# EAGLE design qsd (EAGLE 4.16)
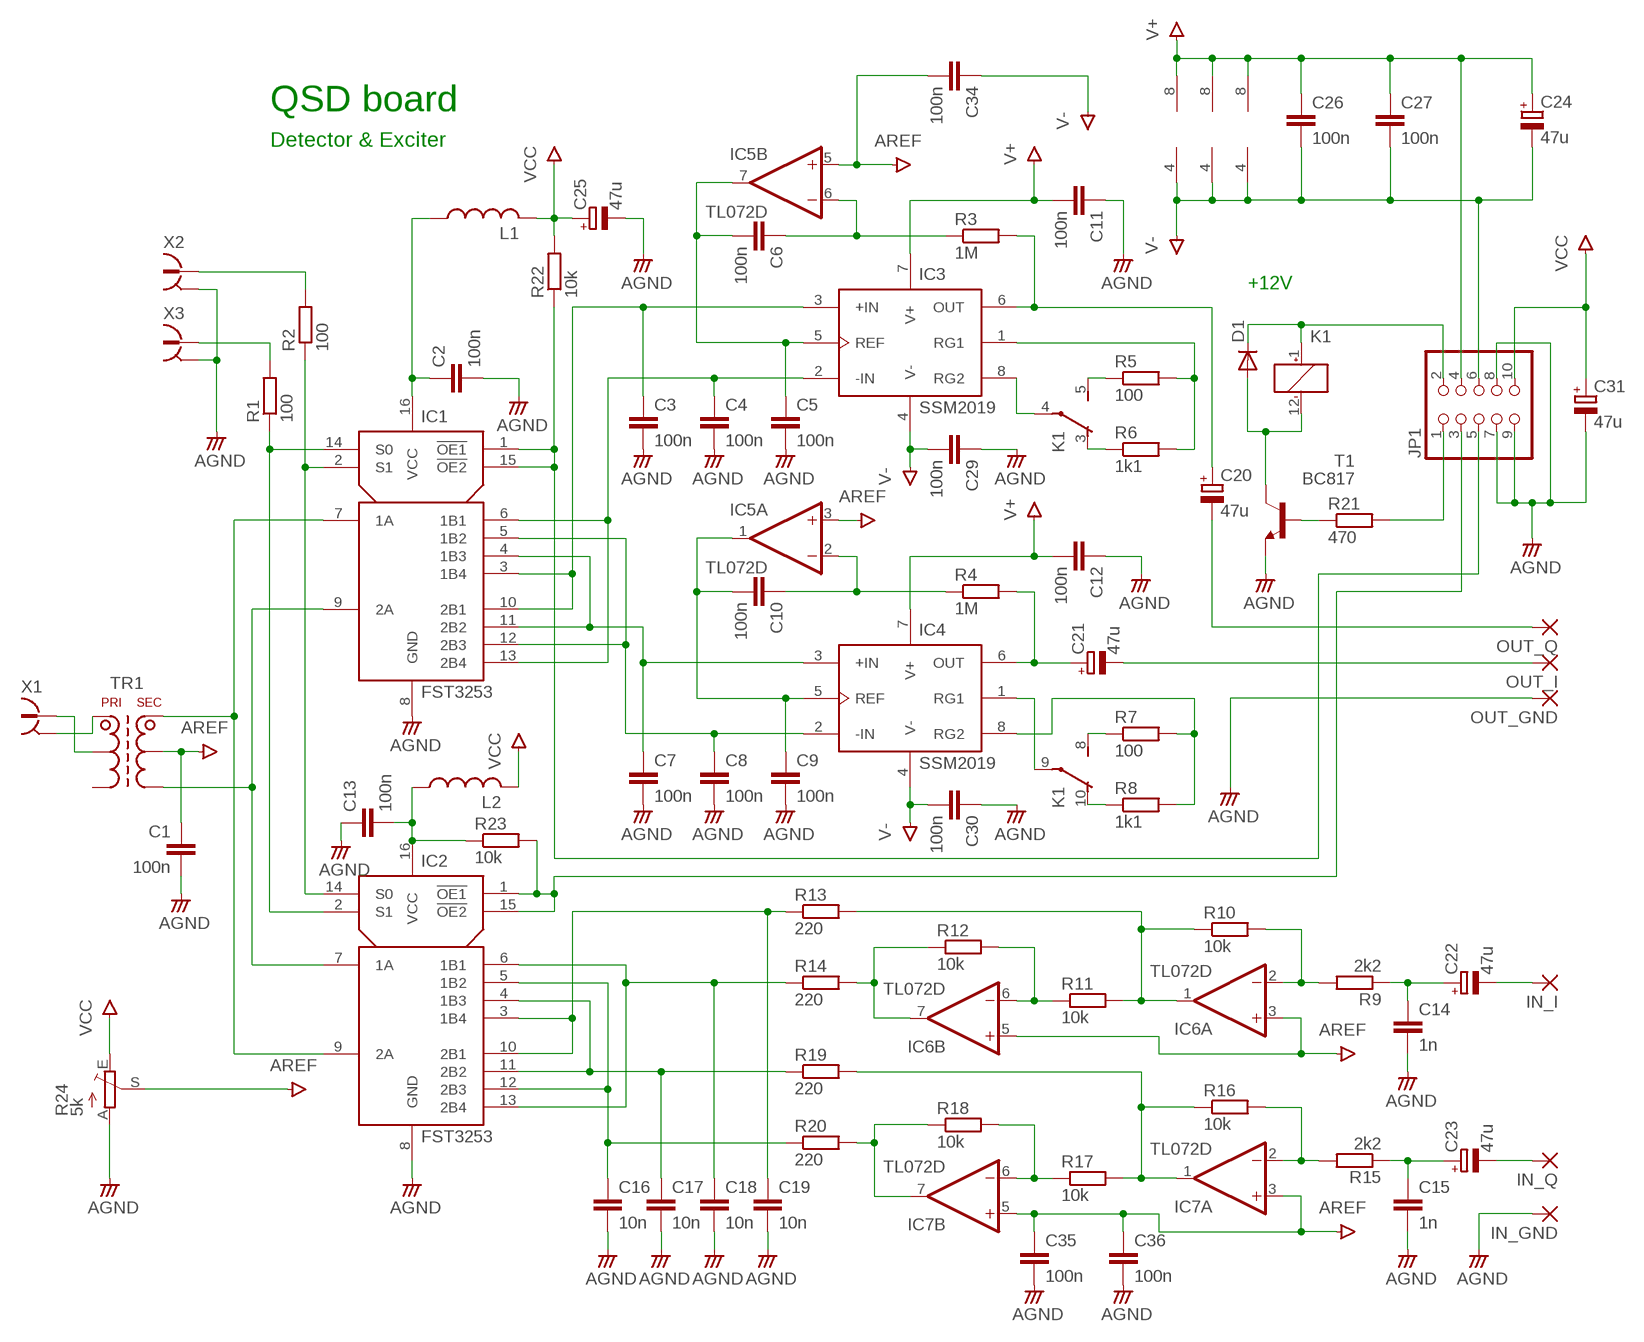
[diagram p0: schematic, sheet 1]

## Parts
C1  100n  C-EUC1206  [C1206]
C2  100n  C-EUC1206  [C1206]
C3  100n  C-EUC1206  [C1206]
C4  100n  C-EUC1206  [C1206]
C5  100n  C-EUC1206  [C1206]
C6  100n  C-EUC1206  [C1206]
C7  100n  C-EUC1206  [C1206]
C8  100n  C-EUC1206  [C1206]
C9  100n  C-EUC1206  [C1206]
C10  100n  C-EUC1206  [C1206]
C11  100n  C-EUC1206  [C1206]
C12  100n  C-EUC1206  [C1206]
C13  100n  C-EUC1206  [C1206]
C14  1n  C-EUC0805  [C0805]
C15  1n  C-EUC0805  [C0805]
C16  10n  C-EUC1206  [C1206]
C17  10n  C-EUC1206  [C1206]
C18  10n  C-EUC1206  [C1206]
C19  10n  C-EUC1206  [C1206]
C20  47u  CPOL-EUC  [PANASONIC_C]
C21  47u  CPOL-EUC  [PANASONIC_C]
C22  47u  CPOL-EUC  [PANASONIC_C]
C23  47u  CPOL-EUC  [PANASONIC_C]
C24  47u  CPOL-EUC  [PANASONIC_C]
C25  47u  CPOL-EUC  [PANASONIC_C]
C26  100n  C-EUC1206  [C1206]
C27  100n  C-EUC1206  [C1206]
C29  100n  C-EUC1206  [C1206]
C30  100n  C-EUC1206  [C1206]
C31  47u  CPOL-EUC  [PANASONIC_C]
C34  100n  C-EUC1206  [C1206]
C35  100n  C-EUC1206  [C1206]
C36  100n  C-EUC1206  [C1206]
D1  PMLL4150  [SOD80C]
IC1  FST3253  [SO16]
IC2  FST3253  [SO16]
IC3  SSM2019  [SO08]
IC4  SSM2019  [SO08]
IC5  TL072D  [SO08]
IC6  TL072D  [SO08]
IC7  TL072D  [SO08]
IN_GND  SMD2  [SMD1,27-2,54]
IN_I  SMD2  [SMD1,27-2,54]
IN_Q  SMD2  [SMD1,27-2,54]
JP1  PINHD-2X5  [2X05]
K1  TX2SOSA-12V  [TX2SA]
L1  L-US0207/7  [0207/7]
L2  L-US0207/7  [0207/7]
OUT_GND  SMD2  [SMD1,27-2,54]
OUT_I  SMD2  [SMD1,27-2,54]
OUT_Q  SMD2  [SMD1,27-2,54]
R1  100  R-EU_R1206  [R1206]
R2  100  R-EU_R1206  [R1206]
R3  1M  R-EU_R1206  [R1206]
R4  1M  R-EU_R1206  [R1206]
R5  100  R-EU_R1206  [R1206]
R6  1k1  R-EU_R1206  [R1206]
R7  100  R-EU_R1206  [R1206]
R8  1k1  R-EU_R1206  [R1206]
R9  2k2  R-EU_R1206  [R1206]
R10  10k  R-EU_R1206  [R1206]
R11  10k  R-EU_R1206  [R1206]
R12  10k  R-EU_R1206  [R1206]
R13  220  R-EU_R1206  [R1206]
R14  220  R-EU_R1206  [R1206]
R15  2k2  R-EU_R1206  [R1206]
R16  10k  R-EU_R1206  [R1206]
R17  10k  R-EU_R1206  [R1206]
R18  10k  R-EU_R1206  [R1206]
R19  220  R-EU_R1206  [R1206]
R20  220  R-EU_R1206  [R1206]
R21  470  R-EU_R1206  [R1206]
R22  10k  R-EU_R1206  [R1206]
R23  10k  R-EU_R1206  [R1206]
R24  5k  TRIM_EU-S64W  [S64W]
T1  BC817  BC817-16-NPN-SOT23-BEC  [SOT23-BEC]
TR1  TT1-6  [MINICIRCUITS-W38]
X1  ST-SMB-V  [ST-SMB-V]
X2  ST-SMB-V  [ST-SMB-V]
X3  ST-SMB-V  [ST-SMB-V]

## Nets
AREF: C1.1 C34.2 C35.1 C36.1 IC5.3(A:+IN) IC5.5(B:+IN) IC6.3(A:+IN) IC6.5(B:+IN) IC7.3(A:+IN) IC7.5(B:+IN) R24.S TR1.2(ST)
N$1: TR1.5(PT) X1.1
N$2: TR1.4(P1) X1.2(GND)
N$3: IC1.14(S0) IC2.2(S1) R1.1
N$4: IC1.2(S1) IC2.14(S0) R2.1
N$5: IC1.7(1A) IC2.9(2A) TR1.3(S1)
N$6: IC1.9(2A) IC2.7(1A) TR1.1(S2)
N$7: IC1.1(!OE1) IC1.15(!OE2) JP1.5 R22.1
N$8: IC2.1(!OE1) IC2.15(!OE2) JP1.3 R23.2
N$9: C18.1 IC2.6(1B1) IC2.13(2B4) R14.1
N$10: C19.1 IC2.3(1B4) IC2.10(2B1) R13.1
N$14: C7.1 IC1.4(1B3) IC1.11(2B2) IC4.3(+IN)
N$15: C8.1 IC1.5(1B2) IC1.12(2B3) IC4.2(-IN)
N$16: C4.1 IC1.6(1B1) IC1.13(2B4) IC3.2(-IN)
N$17: C2.1 IC1.16(VCC) L1.1
N$19: C6.1 IC5.6(B:-IN) R3.1
N$23: C21.+ IC4.6(OUT) R4.2
N$24: IC3.8(RG2) K1.4(1:P)
N$25: R2.2 X2.1
N$26: R1.2 X3.1
N$28: K1.8(2:S) R7.1
N$29: K1.10(2:O) R8.1
N$30: K1.3(1:O) R6.1
N$31: K1.5(1:S) R5.1
N$32: IC4.8(RG2) R7.2 R8.2
N$33: IC3.1(RG1) R5.2 R6.2
N$35: D1.A K1.12(_:-) T1.C
N$36: C13.2 IC2.16(VCC) L2.1 R23.1
N$37: IC7.6(B:-IN) R17.1 R18.2
N$38: C15.1 C23.+ R15.1
N$39: IC7.1(A:OUT) R16.1 R17.2 R19.2
N$40: IC6.2(A:-IN) R9.2 R10.2
N$41: IC6.6(B:-IN) R11.1 R12.2
N$42: IC6.7(B:OUT) R12.1 R14.2
N$43: IC6.1(A:OUT) R10.1 R11.2 R13.2
N$45: IC7.7(B:OUT) R18.1 R20.2
N$46: C14.1 C22.+ R9.1
N$47: C20.- OUT_Q.1(P)
N$48: C21.- OUT_I.1(P)
N$49: C20.+ IC3.6(OUT) R3.2
N$50: C22.- IN_I.1(P)
N$51: C23.- IN_Q.1(P)
N$53: R21.1 T1.B
N$55: JP1.1 R21.2
N$98: C17.1 IC2.4(1B3) IC2.11(2B2) R19.1
N$106: C16.1 IC2.5(1B2) IC2.12(2B3) R20.1
N$132: C9.1 C10.2 IC4.5(REF) IC5.1(A:OUT)
N$135: C10.1 IC5.2(A:-IN) R4.1
N$161: C24.- C26.2 C27.2 C29.2 C30.2 C34.1 IC3.4(V-) IC4.4(V-) IC5.4(P:V-) IC6.4(P:V-) IC7.4(P:V-) JP1.6 ; supply symbol labelled V-
N$207: D1.C JP1.2 K1.1(_:+)
N$211: C25.+ C31.+ JP1.10 L1.2 L2.2 R22.2 R24.E ; supply symbol labelled VCC
N$218: C11.2 C12.2 C24.+ C26.1 C27.1 IC3.7(V+) IC4.7(V+) IC5.8(P:V+) IC6.8(P:V+) IC7.8(P:V+) JP1.4 ; supply symbol labelled V+
N$221: IC4.1(RG1) K1.9(2:P)
N$226: C5.1 C6.2 IC3.5(REF) IC5.7(B:OUT)
N$248: IC7.2(A:-IN) R15.2 R16.2
N$315: C1.2 C2.2 C3.2 C4.2 C5.2 C7.2 C8.2 C9.2 C11.1 C12.1 C13.1 C14.2 C15.2 C16.2 C17.2 C18.2 C19.2 C25.- C29.1 C30.1 C31.- C35.2 C36.2 IC1.8(GND) IC2.8(GND) IN_GND.1(P) JP1.7 JP1.8 JP1.9 OUT_GND.1(P) R24.A T1.E X2.2(GND) X3.2(GND) ; supply symbol labelled AGND
N$325: C3.1 IC1.3(1B4) IC1.10(2B1) IC3.3(+IN)
Unconnected: TR1.6(P2)

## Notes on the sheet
- QSD board
- Detector & Exciter
- +12V

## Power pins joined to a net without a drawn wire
N$315: X1.3(GND) X1.4(GND) X1.5(GND) X2.3(GND) X2.4(GND) X2.5(GND) X3.3(GND) X3.4(GND) X3.5(GND)

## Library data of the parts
C1-C19 C26 C27 C29 C30 C34-C36 = rcl:C-EU: CAPACITOR, European symbol
C20-C25 C31 = rcl:CPOL-EU: POLARIZED CAPACITOR, European symbol
D1 = diode:PMLL4150: DIODE
IC1 IC2 = receiver:FST3253
IC3 IC4 = receiver:SSM2019
IC5-IC7 = linear:TL072: OP AMP
IN_GND IN_I IN_Q OUT_GND OUT_I OUT_Q = wirepad:SMD2: SMD PAD
JP1 = pinhead:PINHD-2X5: PIN HEADER
K1 = relay:TX2SO?-*: 2 AMP. HIGH CAPACITY RELAY NAiS WITH HIGH SURGE VOLTAGE & HIGH BREAKDOWN VOLTAGE Source: http://www.mew-europe.com/.. en_ds_61022_0001.pdf
L1 L2 = rcl:L-US: INDUCTOR, American symbol
R1-R23 = rcl:R-EU_: RESISTOR, European symbol
R24 = pot:TRIM_EU-: POTENTIOMETER
T1 = transistor:*-NPN-: NPN Transistror
TR1 = receiver:TT1-6
X1-X3 = con-coax:ST-SMB-V: MALE SMB CONNECTOR Radiall distributor RS 193-8855G7

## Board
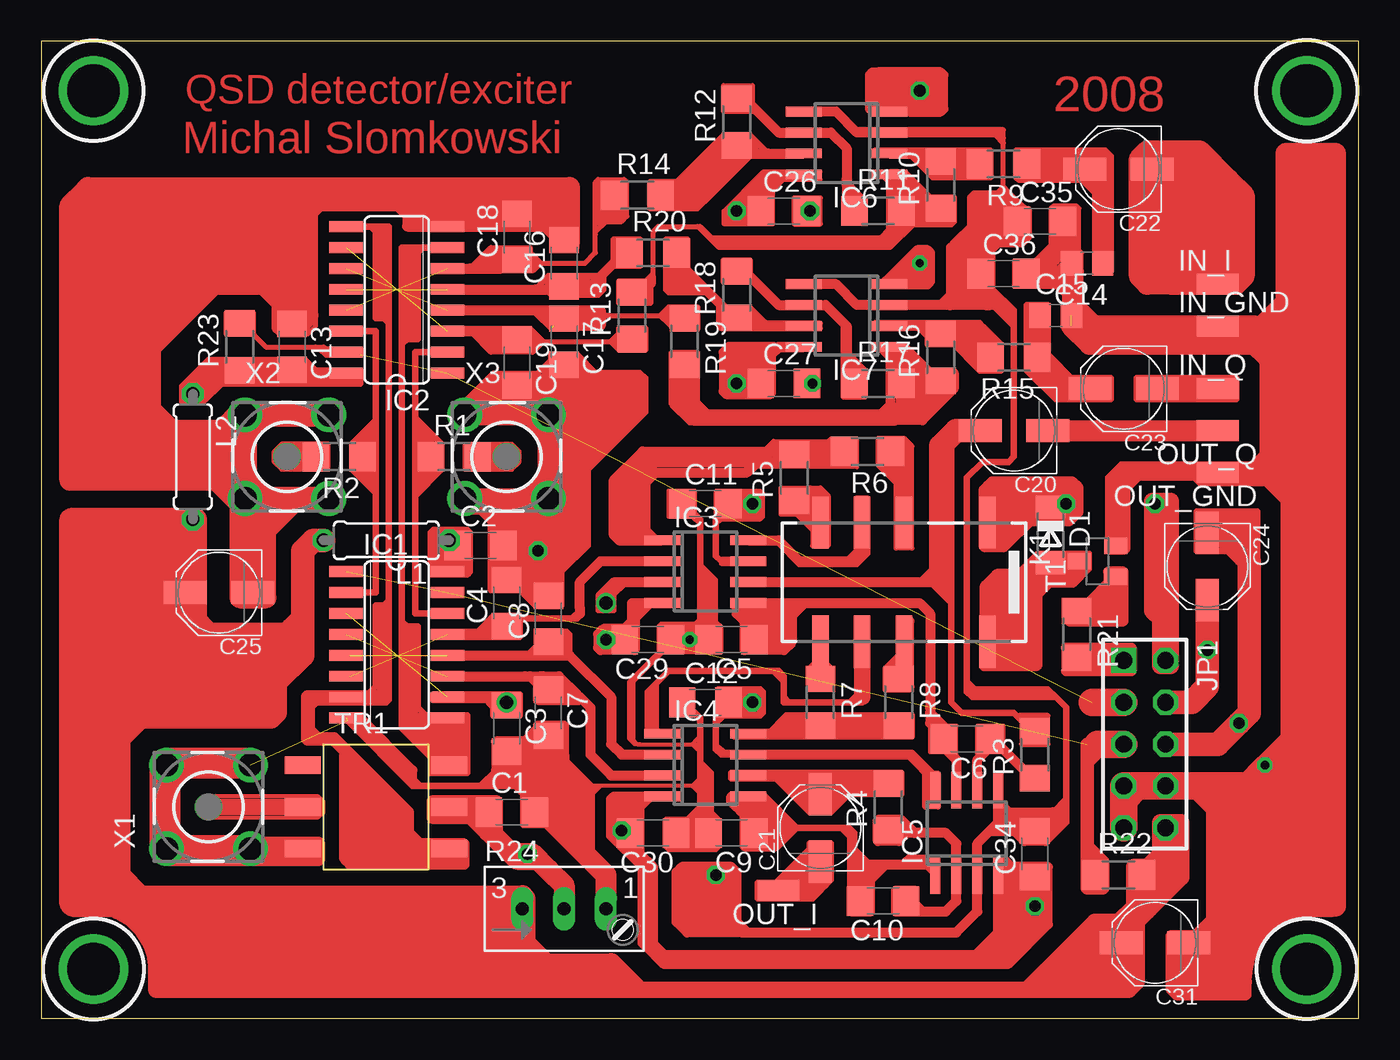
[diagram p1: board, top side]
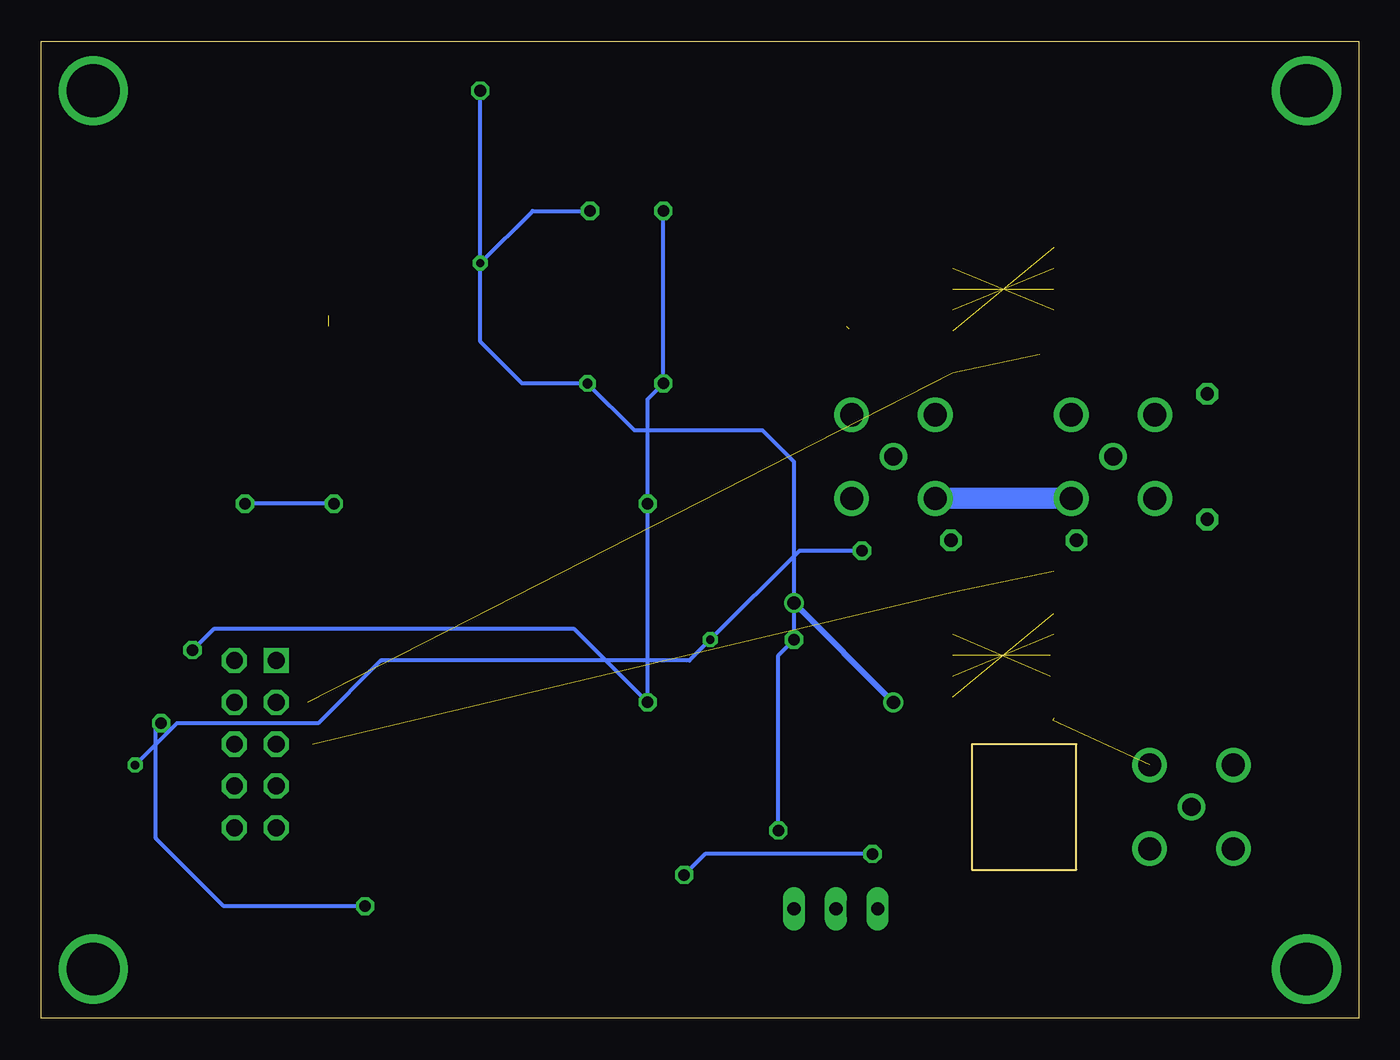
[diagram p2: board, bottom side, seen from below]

Size 79.99 x 59.36 mm. Coordinates in mm from the lower left corner, seen from the top.
Outline: 0,0 79.99,0 79.99,59.36 0,59.36 0,0
Copper layers (1*16): Top 0.035mm / dielectric 1.5mm / Bottom 0.035mm
Design rules "default": minimum track width 10mil, minimum drill 24mil, track to track 8mil, track to pad 8mil, pad to pad 8mil, via to via 8mil, smd to smd 8mil, copper to edge 40mil, drill to drill 8mil, minimum pad ring 10mil, minimum via ring 8mil, stop-mask expansion 4mil, vias tented up to drill 0mil, thermal gap 10mil

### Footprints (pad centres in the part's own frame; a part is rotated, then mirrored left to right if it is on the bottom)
C1206 = smd 1.6 x 1.8: 1 -1.4,0; 2 1.4,0
C0805 = smd 1.3 x 1.5: 1 -0.95,0; 2 0.95,0
PANASONIC_C = smd 2.6 x 1.4: + 2.05,0; - -2.05,0
SOD80C = smd 1.4 x 1.8: A 1.7,0; C -1.7,0
SO16 = smd 0.66 x 2.032: 1 -4.445,-3.073; 2 -3.175,-3.073; 3 -1.905,-3.073; 4 -0.635,-3.073; 5 0.635,-3.073; 6 1.905,-3.073; 7 3.175,-3.073; 8 4.445,-3.073; 9 4.445,3.073; 10 3.175,3.073; 11 1.905,3.073; 12 0.635,3.073; 13 -0.635,3.073; 14 -1.905,3.073; 15 -3.175,3.073; 16 -4.445,3.073
SO08 = smd 0.6 x 2.2: 1 -1.905,-2.6; 2 -0.635,-2.6; 3 0.635,-2.6; 4 1.905,-2.6; 5 1.905,2.6; 6 0.635,2.6; 7 -0.635,2.6; 8 -1.905,2.6
SMD1,27-2,54 = smd 1.27 x 2.54: 1 0,0
2X05 = drill 1.016 square: 1 -5.08,-1.27 | drill 1.016 octagon: 2 -5.08,1.27; 3 -2.54,-1.27; 4 -2.54,1.27; 5 0,-1.27; 6 0,1.27; 7 2.54,-1.27; 8 2.54,1.27; 9 5.08,-1.27; 10 5.08,1.27
TX2SA = smd 1 x 3.16: 1 -5.08,-3.62; 3 0,-3.62; 4 2.54,-3.62; 5 5.08,-3.62; 8 5.08,3.62; 9 2.54,3.62; 10 0,3.62; 12 -5.08,3.62
0207/7 = drill 0.813 octagon: 1 -3.81,0; 2 3.81,0
R1206 = smd 1.6 x 1.803: 1 -1.422,0; 2 1.422,0
S64W = drill 0.813 long: A 2.54,1.27; E -2.54,1.27; S 0,1.27
SOT23-BEC = smd 1 x 1.4: B -0.95,-1.1; C 0,1.1; E 0.95,-1.1
MINICIRCUITS-W38 = smd 1.067 x 2.184: 1 -2.54,6.35; 2 0,6.35; 3 2.54,6.35; 4 2.54,-2.54; 5 0,-2.54; 6 -2.54,-2.54
ST-SMB-V = drill 1.1 round: 1 0,0 | drill 1.4 round: 2 -2.54,2.54; 3 2.54,2.54; 4 2.54,-2.54; 5 -2.54,-2.54

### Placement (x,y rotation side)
C1  28.57,12.54 0 top
C2  26.66,28.73 0 top
C3  28.25,17.61 270 top
C4  28.25,25.23 90 top
C5  41.91,23.01 180 top
C6  56.19,16.98 180 top
C7  30.79,18.57 270 top
C8  30.79,24.28 90 top
C9  41.91,11.27 180 top
C10  51.11,7.14 180 top
C11  40.32,31.27 0 top
C12  40.32,19.2 0 top
C13  15.24,40.79 270 top
C14  63.5,45.87 180 top
C15  61.59,42.7 0 top
C16  31.74,45.87 90 top
C17  31.74,41.11 270 top
C18  28.89,47.46 90 top
C19  28.89,39.84 270 top
C20  59.05,35.71 180 top
C21  47.3,11.58 90 top
C22  65.4,51.59 180 top
C23  65.72,38.25 180 top
C24  70.8,27.46 270 top
C25  10.79,25.87 180 top
C26  45.08,49.05 0 top
C27  45.08,38.57 0 top
C29  36.83,23.01 180 top
C30  37.14,11.27 180 top
C31  67.62,4.6 180 top
C34  60.32,10 90 top
C35  60.64,48.41 0 top
C36  58.41,45.24 0 top
D1  61.27,29.36 270 top
IC1  21.58,22.7 270 top
IC2  21.58,43.65 90 top
IC3  40.32,27.14 270 top
IC4  40.32,15.39 270 top
IC5  56.19,11.27 0 top
IC6  48.89,53.17 90 top
IC7  48.89,42.7 90 top
IN_GND  71.43,42.06 270 top
IN_I  71.43,44.6 270 top
IN_Q  71.43,38.25 270 top
JP1  66.99,16.66 270 top
K1  52.38,26.5 180 top
L1  20.95,29.04 180 top
L2  9.2,34.12 270 top
OUT_GND  71.43,33.17 90 top
OUT_I  44.76,7.77 90 top
OUT_Q  71.43,35.71 90 top
R1  25.08,34.12 0 top
R2  18.09,34.12 180 top
R3  60.32,16.03 90 top
R4  51.43,12.85 90 top
R5  45.72,32.85 90 top
R6  50.16,34.44 180 top
R7  47.3,19.2 270 top
R8  52.07,19.2 270 top
R9  58.41,51.91 180 top
R10  54.61,50.63 90 top
R11  50.8,49.05 0 top
R12  42.22,54.45 90 top
R13  35.87,42.7 90 top
R14  36.19,50 0 top
R15  59.05,40.16 180 top
R16  54.61,40.16 90 top
R17  50.8,38.57 0 top
R18  42.22,43.97 90 top
R19  39.05,41.11 270 top
R20  37.14,46.51 0 top
R21  62.86,23.33 270 top
R22  65.4,8.73 0 top
R23  12.06,40.79 90 top
R24  31.74,5.39 0 top
T1  64.13,27.77 90 top
TR1  18.41,12.85 270 top
X1  10.16,12.85 90 top
X2  14.92,34.12 0 top
X3  28.25,34.12 0 top

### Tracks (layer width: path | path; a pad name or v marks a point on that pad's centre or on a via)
AREF  (via drill 0.7)
  Top 0.254: 28.73,9.84 28.89,10 v29.52,10 | 28.73,9.84
  Top 0.305: 58.1,53.81 58.41,53.49 58.41,53.17 | 58.41,50.32 58.41,53.17 | 58.41,53.17 58.41,53.97 49.53,53.97 | 58.41,53.17 | 58.41,53.17 57.94,53.65
  Top 0.406: 58.1,12.22 61.27,12.22 62.23,13.17 62.23,13.33 | 62.23,13.33 62.23,18.88 61.59,19.52 | 61.59,19.52 56.51,19.52 56.19,19.84 56.19,20.47 | 56.19,20.47 56.19,32.85 57.15,33.81 58.73,33.81 59.05,34.12 59.05,41.9 | 56.37,45 56.37,44.75 57.78,43.33 59.05,42.06 59.05,41.9 | 62.23,13.33 62.23,11.9 61.11,10.79 | 62.23,13.33 | 61.43,12.54 62.23,13.33 | 59.05,41.9 59.05,43.02 57.78,44.28 | 55.24,43.97 55.08,43.97 54.45,43.33 | 61.59,19.52 | 61.59,19.52 61.11,20 56.67,20 56.19,20.47
  Top 0.61: 58.1,13.17 58.1,12.22 58.1,11.9 57.78,11.58 | 57.78,11.58 56.83,10.63 IC5.3 56.83,6.5 55.56,5.23 42.86,5.23 | C34.2 57.65,11.4 57.78,11.58 | IC6.5 48.26,55.08 49.53,53.81 IC6.3 58.1,53.81 | IC7.5 48.26,44.6 49.53,43.33 IC7.3 54.45,43.33 55.08,43.33 | 58.41,49.05 58.41,48.41 57.15,47.14 | 58.41,49.05 58.41,50.32 | C36.1 56.37,45 55.24,44.6 55.24,44.44 | 55.08,43.33 55.24,43.33 55.24,43.97 55.24,44.44 | 58.41,49.05 C35.1 | 42.86,5.23 42.54,5.23 41.59,6.18 41.59,8.73 v40.95,8.73 | 58.1,13.17 IC5.5 | 58.1,13.17 58.73,12.54 61.43,12.54 | 42.86,5.23 42.22,5.87 42.22,8.88 41.91,9.2 38.89,9.2 38.57,8.88 38.57,5.87 39.21,5.23 42.86,5.23 | 58.41,50.32 | 58.41,50.32 59.53,49.21 | 59.53,49.21 | 59.53,49.21 59.69,49.05 59.84,49.05 59.84,47.46 59.53,47.14 | 58.41,47.14 59.53,47.14 | 57.15,47.14 58.41,47.14 | 58.41,47.14 58.1,47.14 57.62,46.67 57.62,43.49 | 57.3,43.33 55.08,43.33 | 57.3,43.33 57.62,43.33 | 57.78,43.33 57.3,43.33 | 55.56,47.14 57.15,47.14 | 55.56,47.14 55.24,46.82 55.24,44.44 | 58.41,50.32 58.1,50 56.67,50 56.51,49.84 56.51,48.41 | 56.51,48.41 56.51,48.09 55.56,47.14 | 56.51,48.41 56.51,47.3
  Top 0.813: 27.62,10.95 27.3,10.95 26.03,12.22 23.81,12.22 23.81,13.17 27.62,13.17 27.62,11.27
  Top 1.016: C1.1 26.98,12.54 26.66,12.85 TR1.2
  Top 1.27: C1.1 27.17,11.4 27.62,10.95 28.73,9.84 28.89,9.68 30.16,9.68 30.79,9.04 | 30.79,9.04 31.74,8.09 R24.S | 30.79,9.04 29.84,10 28.73,10
  Bottom 0.254: v40.95,8.73 39.68,10 v29.52,10
N$1
  Top 1.016: X1.1 TR1.5
N$2
  Top 1.016: X1.2 TR1.4
N$3
  Top 0.406: IC2.2 22.7,40.48 22.7,34.12 | 22.7,34.12 22.7,24.6 IC1.14 24.76,24.6 | 22.7,34.12 R1.1
N$4
  Top 0.406: IC2.14 20.31,41.74 20.31,36.35 | 20.31,31.9 20.31,25.87 IC1.2 | 20.31,31.9 20.31,34.12 | 20.31,34.12 20.31,36.35 | 20.31,34.12 R2.1 | 20.31,36.35 18.89,34.92 18.89,33.33 20.31,31.9
N$5
  Top 0.254: 17.14,16.98 16.5,17.61 16.5,18.88 | 16.5,18.88 16.5,19.2 | 16.5,18.88 16.82,19.2 20.95,19.2
  Top 0.406: 21.11,20 21.11,19.52 20.79,19.52 18.73,19.52 | 21.11,20 21.11,25.55 | 21.11,25.55 21.11,41.9 | 21.11,41.9 21.11,48.09 20,48.09 | 18.09,48.09 IC2.9 20,48.09 | 21.11,20 21.11,19.36 20.95,19.2 16.5,19.2 | 21.11,25.55 21.11,25.39 20.79,25.08 20.31,25.08 20.31,20.15 19.84,19.68 | 21.11,41.9 21.11,42.22 20.79,42.54 20.31,42.54 20.31,47.78 20,48.09
  Top 0.61: IC1.7 18.73,19.52 16.5,19.52 16.19,19.2 | 22.86,10.63 25.71,10.63 25.71,9.36 18.73,9.36 18.41,9.68 18.41,16.03
  Top 0.813: TR1.3 22.22,10.31 22.22,11.27 | 16.19,18.88 16.19,16.98 17.14,16.98 17.77,16.98 22.22,12.54 22.22,11.27 | 16.19,18.88 16.19,19.2 | 22.86,10.63 22.22,11.27 | 16.19,18.88 16.19,19.52 20.79,19.52
N$6
  Top 0.406: IC1.9 21.9,18.25 21.9,18.41 | 21.9,18.41 21.9,24.44 | 21.9,24.44 21.9,40.95 | 21.9,40.95 21.9,46.82 23.17,46.82 | 24.76,46.82 IC2.7 23.17,46.82 | 21.9,18.41 21.9,17.61 23.65,15.87 23.65,14.92 25.87,14.92 25.87,18.41 23.33,18.41 | 23.33,18.41 23.01,18.41 | 21.9,24.44 21.9,24.12 22.22,23.81 22.86,23.81 22.86,18.88 23.33,18.41 | 21.9,40.95 22.22,41.27 22.86,41.27 22.86,46.51 23.17,46.82
  Top 0.61: IC1.9 24.66,15.49 TR1.1
N$7  (2 unrouted)
  Top 0.813: 63.5,8.41 R22.1 | 64.13,16.66 63.5,16.66 63.5,10.31 | 63.5,8.41 63.5,10.31 | 63.5,10.31 63.65,10.31 64.45,9.52 64.45,7.93 63.5,7.93 63.5,8.41
  Top 1.676: 64.13,16.66 JP1.5
N$8  (2 unrouted)
  Top 0.305: R23.2 12.23,42.21 13.65,40.79 16.66,40.79 | 16.66,40.79 17.14,40.48 IC2.15 18.73,40.48 | 16.66,40.79 17.14,40.79 17.3,40.63
  Top 0.406: 17.3,40.63 19.36,40.63 19.36,40.32 17.3,40.32 16.98,40.63
  Top 1.676: 63.81,19.2 JP1.3
N$9  (1 unrouted)
  Top 0.305: 28.89,46.51 28.89,45.87 30.32,45.87 | 30.32,45.87 33.02,45.87 33.65,46.51 33.65,47.62 | R14.1 34.92,50 33.65,48.73 33.65,48.57 | 33.65,47.62 33.65,48.57 | 26.03,45.55 27.3,46.82 29.68,46.82 29.68,46.51 30.32,45.87 | 30.32,45.87 | 30.32,45.87 29.84,45.4 25.55,45.4 | 33.65,47.62 33.65,47.78 34.29,48.41 35.24,48.41 35.55,48.73 35.55,50.79 35.4,50.95 33.81,50.95 33.65,50.79 33.65,48.57
  Top 0.61: C18.1 28.89,46.51 27.93,45.55 26.03,45.55 IC2.6
N$10  (1 unrouted)
  Top 0.305: R13.1 35.87,41.43 35.55,41.11 34.6,41.11 30.47,41.11 | 28.89,41.11 30.47,41.11 | 25.39,41.9 29.68,41.9 30.47,41.11 | 30.47,41.11 29.84,40.48 27.3,40.48 26.19,41.59
  Top 0.406: 35.08,41.59 35.08,41.9 36.67,41.9 36.67,40.63 35.08,40.63 34.6,41.11 35.08,41.59
  Top 0.61: IC2.10 18.41,46.82 | C19.1 28.89,41.11 28.25,41.74 IC2.3
N$11
  Top 0.813: 22.38,41.59 22.38,46.51
N$12
  Top 0.813: 20.63,43.02 20.63,47.78
N$14  (1 unrouted)
  Top 0.61: IC1.11 29.36,20.79 | 29.36,20.79 30.32,20.79 | 30.32,20.79 30.47,20.79 30.79,20.47 C7.1 30.98,19.97 31.43,19.52 32.7,19.52 33.33,18.88 33.33,16.03 34.6,14.76 IC4.3 | 30.32,20.79 31.43,20.79 32.54,19.68 31.9,19.68 31.59,20 | 29.36,20.79 29.68,20.79 30,20.47 30.16,20.47 30.16,19.36 32.7,19.36
N$15  (1 unrouted)
  Top 0.61: 18.73,22.06 IC1.5 18.41,22.06 | IC1.12 30.47,22.06 | 30.47,22.06 31.43,23.01 C8.1 31.3,22.88 30.47,22.06 | 30.47,22.06 32.06,22.06 34.6,19.52 34.6,16.66 35.24,16.03 IC4.2 37.78,16.03
N$16  (1 unrouted)
  Top 0.254: C4.1 28.25,24.28
  Top 0.406: IC1.6 18.73,20.79 | 28.25,24.28 29.2,24.28 | 29.2,24.28 32.22,24.28 | 32.22,24.28 32.54,24.28 | 32.54,24.28 32.7,24.6 | 32.7,24.92 32.7,24.76 32.22,24.28 | 32.54,24.28 32.7,24.44 | 29.05,24.44 | 29.05,24.44 29.2,24.28 | 29.2,24.28 29.05,24.12 | 29.05,24.12 28.89,23.96 | 29.05,24.12 29.05,23.17 23.97,23.17 | 29.05,24.44 27.46,24.44 26.51,23.49
  Top 0.61: C4.1 28.25,23.33 IC1.13 | 32.7,24.6 32.7,24.92 32.7,26.5 33.97,27.77 IC3.2 37.78,27.77
N$17
  Top 0.61: IC1.16 24.76,27.14 25.27,27.64 25.27,28.09 C2.1
  Top 1.27: 25.27,28.09 24.76,28.09 L1.1
N$18
  Top 0.406: 47.94,10.63 47.94,8.41 46.83,7.3 43.49,7.3 43.49,8.25 44.6,8.25 46.67,10.31 46.67,10.63
N$19
  Top 0.61: IC5.6 56.83,15.71 57.46,16.34 C6.1 57.78,16.98 60.32,14.44 R3.1
N$20  (via drill 3.2 pad 3.81)
  other vias: 76.83,56.35
N$21
  Top 0.305: 16.66,42.54 16.66,42.06 16.19,41.59 14.44,41.59 14.12,41.9 14.12,43.33 13.33,44.13
N$22
  Top 0.813: 45.24,8.41 46.83,10
N$23
  Top 0.61: IC4.6 47.62,14.76 | 47.62,13.49 C21.+ 47.62,14.76 | R4.2 52.07,14.76 47.62,14.76
N$24
  Top 0.406: 48.89,27.77 49.53,28.41 49.53,31.58 50.16,31.58 50.16,28.25 49.53,27.62 46.03,27.62 44.76,28.89
  Top 0.61: IC3.8 44.76,29.04 46.03,27.77 48.89,27.77 49.53,27.77 49.84,28.09 K1.4 49.84,30.63
N$25
  Top 1.27: 16.82,34.12 R2.2 X2.1
N$26
  Top 1.27: R1.2 X3.1
N$27
  Top 0.406: 52.07,23.96 52.22,23.96
N$28
  Top 1.016: 47.3,20.47 R7.1 K1.8
N$29
  Top 1.016: R8.1 52.38,20.79 K1.10
N$30
  Top 1.016: R6.1 51.43,34.44 52.38,33.49 K1.3
N$31
  Top 0.813: K1.5 47.3,30.16 46.03,31.43 R5.1
N$32
  Top 0.406: 51.11,18.41 51.27,18.41 | 51.11,18.41 45.24,18.41 44.13,17.3 | 51.11,18.41 52.86,18.41 52.86,17.14 42.06,17.14
  Top 0.61: IC4.8 44.13,17.3 46.98,17.3 47.3,17.61
  Top 1.27: R7.2 47.3,17.61 47.77,17.78 R8.2
N$33
  Top 0.61: 37.3,29.04 36.67,29.04 36.67,29.68 | R5.2 45.72,34.12 45.4,33.81 43.49,33.81 42.86,33.17 37.3,33.17 36.67,32.54 36.67,29.84 36.67,29.68 | 37.3,29.04 IC3.1 | 37.3,29.04 36.35,29.04 35.08,29.04 34.76,29.36 34.76,32.7 36.51,34.44 44.29,34.44 | 37.3,29.04 36.67,29.68
  Top 1.422: R5.2 45.72,34.44 R6.2
N$34
  Top 0.406: 71.43,30.79 70.16,30.79 70.16,28.41 72.23,28.41 | 71.43,30.79 71.43,30.16 | 71.43,30.79 73.81,30.79 73.81,27.93
N$35
  Top 1.016: K1.12 57.46,26.19 58.1,26.82 61.27,26.82 D1.A 61.27,27.77 T1.C
N$36
  Top 0.61: IC2.16 15.55,39.2 15.24,39.52
  Top 1.27: C13.2 15.24,39.52 15.08,39.37 R23.1
  Top 1.422: L2.1 9.2,38.25 10.32,39.37 R23.1
N$37
  Top 0.61: R18.2 42.22,45.24 42.86,45.24 44.76,43.33 IC7.6 47.62,43.33 48.89,42.06 48.89,38.25 49.53,38.57 R17.1
N$38
  Top 1.27: C23.+ 62.54,38.25 60.64,40.16 | 60.64,40.16 R15.1 | C15.1 60.64,40.16
N$39
  Top 0.61: 51.75,40.79 IC7.1 51.49,40.73 51.75,40.48 51.75,38.25 52.38,38.25 | 51.75,40.79 52.38,40.79 52.38,38.57 | 51.75,40.79 52.38,40.79 53.81,39.36 | 53.81,39.36 | 53.81,39.36 53.97,39.2 55.4,39.2 55.4,38.25 53.49,36.35 51.27,36.35
  Top 1.016: 52.38,38.25 52.38,37.14 51.75,36.51 39.68,36.51 39.05,37.46 R19.2
  Top 1.27: R17.2 52.38,38.57 52.55,38.74 R16.1
N$40
  Top 0.61: R10.2 54.61,51.91 53.97,52.54 IC6.2
  Top 1.27: R9.2 56.83,51.91 56.68,52.06 R10.2
N$41
  Top 0.61: R12.2 42.22,56.03 42.54,55.71 42.86,55.71 44.76,53.81 IC6.6 47.94,53.81 48.89,52.86 48.89,50.95 | R11.1 49.53,49.05 48.89,49.68 48.89,50.95 | 48.89,50.95 48.89,50.63 49.84,49.68
N$42
  Top 0.406: 43.02,53.65 | 44.13,52.54 43.02,53.65 | 43.02,53.65 41.43,53.65 38.57,50.79 36.98,50.79 36.98,49.21 39.84,49.21 43.02,52.38
  Top 0.61: 42.22,52.54 44.13,52.54 IC6.7
  Top 1.27: R14.2 40,50 42.22,52.22 42.22,52.54 R12.1 42.22,53.17
N$43
  Top 0.254: 50.95,51.27 51.43,50.79 51.43,47.94 50.95,47.46 40.64,47.46 | 53.02,48.25 | 53.02,48.25 51.59,46.82 41.11,46.82 39.84,48.09
  Top 0.305: R13.2 36.34,44.12 36.98,44.76 37.14,44.92 37.14,45.08 | 37.14,45.08 37.14,45.24 | 37.14,45.24 37.14,47.78 37.46,48.09 39.84,48.09 40,48.09 40.64,47.46 40.95,47.14 41.27,47.14 | 37.14,45.08 37.14,44.6 36.83,44.28 36.83,43.65 | 37.14,45.24 36.51,44.6
  Top 0.406: 53.97,49.84 55.4,49.84 55.4,48.41 55.24,48.25 53.02,48.25 52.7,48.25 52.38,48.25 | 36.98,44.76 36.67,44.76 | 36.98,44.76 35.08,44.76 35.08,43.49 36.98,43.49 36.98,44.76
  Top 0.61: IC6.1 52.07,51.27 52.07,50.63 52.07,49.05 | 52.7,48.25 52.07,47.62
  Top 0.813: 41.27,47.14 51.43,47.14 52.07,47.78 52.07,48.09 52.07,49.05 R11.2
  Top 1.27: R11.2 52.38,49.05 52.55,49.21 R10.1 | 52.07,50.63 52.07,48.09
N$44
  Top 0.406: 51.59,49.84 51.59,50.95
N$45
  Top 0.305: R20.2 38.56,46.04 41.59,43.02 41.91,43.02 42.22,42.7 | 43.81,42.22 47.3,42.22 47.3,41.9 41.27,41.9 41.11,42.06 41.11,43.33 40.32,44.13
  Top 0.406: 37.94,45.71 37.94,47.3 39.21,47.3 39.21,45.55 41.59,43.17 | 37.94,45.71 38.89,45.71 | 37.94,45.71 37.94,44.28 38.1,44.13 40.32,44.13 40.48,44.13
  Top 0.61: R18.1 42.22,42.7 42.86,42.06 45.72,42.06 | 45.72,42.06 IC7.7 | 45.72,42.06 43.97,42.06 43.81,42.22 43.02,43.02
N$46
  Top 1.27: C14.1 64.44,50.32 62.86,51.91
  Top 1.422: C22.+ 63.5,51.59 63.18,51.91 62.86,51.91 R9.1
N$47
  Top 1.27: C20.- OUT_Q.1
N$48
  Top 1.27: C21.- 47.3,8.41 46.67,7.77 OUT_I.1
N$49
  Top 0.406: R3.2 60.17,17.45 59.05,18.57 55.88,18.57 55.24,19.2 55.24,24.76 | 55.24,24.76 55.24,35.08 54.92,26.82 | 55.24,24.76 55.24,25.23 53.97,26.5
  Top 0.61: IC3.6 53.49,26.5 | 53.49,26.5 53.97,26.5 54.29,26.5 | 54.29,26.5 54.92,26.82 | 54.29,26.5 54.61,26.82 | 53.49,26.5 | 53.49,26.5 54.29,27.3
  Top 1.422: C20.+ 55.56,35.71 54.61,34.76 54.61,26.82
N$50
  Top 1.27: C22.- 67.94,51.59 67.94,45.24 68.57,44.6 IN_I.1
N$51
  Top 1.27: C23.- IN_Q.1
N$52  (via drill 3.2 pad 3.81)
  other vias: 3.17,56.35
N$53
  Top 1.016: T1.B 65.23,26.65 63.5,24.92 62.86,24.92 R21.1
N$54  (via drill 3.2 pad 3.81)
  other vias: 3.17,3.01
N$55
  Top 1.422: R21.2 62.86,21.74 JP1.1
N$56  (via drill 3.2 pad 3.81)
  other vias: 76.83,3.01
N$57
  Top 0.254: 10.47,13.49 16.82,13.49 17.14,13.17 17.14,12.54 16.82,12.22 10.47,12.22
N$58
  Top 0.406: 16.82,12.54 16.82,13.17
N$59
  Top 0.813: 7.62,16.03 12.7,16.03
N$60
  Top 0.813: 6.98,10.31 6.98,15.39
N$61
  Top 0.813: 21.9,9.68 25.39,9.68
N$62
  Top 0.813: 13.33,10.63 16.82,10.63 16.82,9.68 7.62,9.68
N$63
  Top 0.813: 7.93,11.58 8.89,10.63
N$64
  Top 0.813: 7.93,14.12 8.89,15.08
N$65
  Top 1.422: 19.04,10 19.04,15.08
N$66
  Top 1.422: 20,10 20,14.12
N$67
  Top 1.422: 20.95,10 20.95,13.17
N$68
  Top 1.422: 21.58,10 21.58,12.54
N$69
  Top 0.813: 20.79,19.84 20.79,24.6
N$70
  Top 1.016: 22.38,18.57 22.38,23.49
N$71
  Top 1.016: 22.54,17.93 24.12,16.34
N$72
  Top 1.016: 23.49,17.93 23.81,17.93 24.44,17.3
N$73
  Top 1.016: 25.39,16.03 25.39,17.93
N$74
  Top 0.254: 25.71,34.92 28.57,34.92 29.05,34.44 29.05,33.81 28.57,33.33 25.71,33.33 25.71,34.92
N$75
  Top 0.254: 27.3,34.76 28.57,34.76 28.89,34.44 28.89,33.81 28.57,33.49 27.3,33.49
N$76
  Top 0.254: 17.46,34.92 14.6,34.92 14.12,34.44 14.12,33.81 14.6,33.33 17.46,33.33 17.46,34.92
N$77
  Top 0.254: 15.87,34.76 14.76,34.76 14.28,34.28 14.28,33.81 14.6,33.49 15.87,33.49
N$78
  Top 0.406: 22.7,36.51 24.28,34.92 24.28,33.33 22.7,31.74
N$79
  Top 0.406: 25.55,26.98 25.39,26.98 | 25.55,26.98 25.87,26.98 26.03,27.14 26.03,29.52 25.87,29.68 23.81,29.68 23.65,29.52 23.65,26.98 25.55,26.98
N$80
  Top 0.813: 23.01,35.87 23.01,35.39 23.49,34.92
N$81
  Top 0.813: 23.81,33.33 23.49,33.33 23.17,33.01 23.17,32.7 23.01,32.54
N$82
  Top 0.813: 20,35.55 20,35.39 19.68,35.08
N$83
  Top 0.813: 19.36,33.49 20,32.85 20,32.7
N$84
  Top 0.406: 12.85,41.59 12.85,42.86 11.27,42.86 11.27,41.59 12.85,41.59
N$85
  Top 0.406: 19.36,39.36 16.66,39.36 16.03,40 10.16,40 8.57,38.41 8.57,37.46 9.84,37.46 10.95,38.57 19.36,38.57 19.36,39.36
N$86
  Top 0.406: 16.19,39.52 16.19,39.68
N$87
  Top 0.406: 15.71,38.89 19.2,38.89
N$88
  Top 0.406: 9.84,37.78 10.79,38.73
N$89
  Top 0.61: 33.65,42.54 30.79,42.54 30.63,42.7
N$90
  Top 0.406: 32.54,44.76 33.17,44.76
N$91
  Top 0.406: 32.86,44.44 32.86,44.28 32.7,44.13
N$92
  Top 0.406: 32.7,44.28 32.7,44.44
N$93
  Top 0.406: 30.79,44.6 30.79,44.76
N$94
  Top 0.406: 29.68,45.71 29.84,45.71
N$95
  Top 0.406: 29.84,46.03 30,46.03
N$96
  Top 1.27: 27.46,46.19 28.41,46.19
N$97
  Top 0.61: 26.66,45.87 26.98,45.87
N$98  (2 unrouted)
  Top 0.305: C17.1 31.74,42.7 34.29,42.7 | R19.1 39.05,42.38 38.73,42.7 37.78,42.7 | 34.29,42.7 34.44,42.7 | 34.44,42.7 37.62,42.7 37.78,42.7 | 30,42.86 30.95,41.9 | 34.44,42.7 34.29,42.7 | 34.29,42.7 34.13,42.86 | 34.29,42.7 34.13,42.54 | 37.78,42.7 38.1,43.02 | 37.78,42.7 38.1,42.38
  Top 0.406: 38.1,42.22 38.41,41.9 39.84,41.9 39.84,43.17 38.1,43.17 | 38.1,42.22 38.1,42.38 38.1,43.02 38.1,43.17 | 37.78,42.86 38.1,43.17 | 37.78,42.86 | 37.78,42.86 37.62,42.7 38.1,42.22
  Top 0.61: C17.1 31.74,42.38 31.11,43.02 | IC2.4 31.11,43.02 | 31.11,43.02 33.97,43.02 33.97,42.06 31.11,42.06
N$99
  Top 0.406: 19.04,17.93 | 22.06,14.92 19.04,17.93
N$100
  Top 0.406: 43.02,44.76 41.43,44.76 41.43,46.03 43.02,46.03 43.02,45.24
N$101
  Top 0.305: 43.18,42.38 42.86,42.7
N$102
  Top 0.305: 41.27,42.06 41.27,43.17
N$103
  Top 1.016: 38.41,44.6 38.41,45.55
N$104
  Top 1.016: 39.68,44.44 39.05,45.08
N$105
  Top 1.016: 38.73,44.44 39.21,44.44
N$106  (1 unrouted)
  Top 0.406: 32.38,43.97 33.81,43.97 34.13,44.28 34.13,45.08 | R20.1 35.24,46.51 34.76,46.03 | 33.65,44.92 33.33,44.6 31.74,44.6 | 33.81,45.08 33.65,44.92 | 33.81,45.08 34.13,45.4 | 34.13,45.4 34.44,45.71 | 34.44,45.71 34.76,46.03 | 31.43,44.28 31.61,44.47 C16.1 | 33.65,44.92 32.7,43.97 | 33.81,45.08 30.79,45.08 30,44.28 | 31.11,43.97 30.95,43.97 30.63,44.28 | 34.44,45.71 36.35,45.71 36.35,47.3 34.76,47.3 34.76,46.03 | 34.13,45.4 34.13,45.08 | 35.08,45.87 34.92,45.87 34.13,45.08
  Top 0.61: C16.1 31.74,44.6 31.43,44.28 30.63,44.28 30,44.28 IC2.5
N$107
  Top 0.406: 33.97,44.92 33.97,44.6 33.65,44.28
N$108
  Top 0.406: 33.81,44.6 33.65,44.6 33.33,44.28
N$109
  Top 0.61: 33.97,48.41 33.97,50.63
N$110
  Top 0.61: 34.29,48.89 35.24,48.89
N$111
  Top 0.61: 34.29,48.57 35.08,48.57
N$112
  Top 0.61: 29.84,40.79 29.84,41.43
N$113
  Top 0.61: 26.82,41.43 28.09,41.43
N$114
  Top 0.813: 27.14,41.11 27.3,40.95 28.09,40.95
N$115
  Top 0.406: 46.67,12.54 47.94,12.54 49.05,13.65 52.22,13.65 52.22,14.92 41.91,14.92 41.91,14.6 44.76,14.6 | 46.67,12.54 | 46.67,12.54 44.6,14.6
N$116
  Top 0.254: 47.3,51.43 43.81,51.43 41.43,49.05 41.43,48.25 44.45,48.25 44.45,50.32 45.08,50.95 47.3,50.95 47.3,51.43
N$117
  Top 0.813: 41.91,48.89 44.13,51.11
N$118
  Top 0.813: 43.65,50 44.6,50.95
N$119
  Top 0.813: 42.86,48.57 41.75,48.57
N$120
  Top 0.305: 45.72,49.84 47.3,49.84 47.3,48.25 45.72,48.25 45.72,49.84
N$121
  Top 0.813: 43.18,53.02 43.02,53.02
N$122
  Top 1.27: 39.05,50.48 41.59,53.02
N$123
  Top 0.813: 45.56,14.12 50.48,14.12
N$124
  Top 0.813: 45.24,14.44 46.51,13.17
N$125
  Top 0.813: 48.57,13.49 48.1,13.49 48.1,13.17
N$126
  Top 0.813: 46.51,13.65 46.83,13.65
N$127
  Top 0.813: 46.03,8.09 47.14,9.2
N$128
  Top 1.27: 43.18,12.85 42.7,12.85
N$129
  Top 1.27: 44.45,11.11 44.45,12.38
N$130
  Top 1.27: 43.33,12.06 44.29,12.06
N$131
  Top 0.61: 54.29,7.93 54.29,9.68 52.7,9.68 52.54,9.52
N$132
  Top 0.406: 45.72,11.58 48.57,11.58 | 48.57,11.58 48.89,11.58 49.21,11.27 | 48.57,11.58 49.05,11.58 49.37,11.27 49.37,10.31 50.16,9.52 | 48.57,11.58 | 48.57,11.58 49.05,11.11 | 53.65,9.52 53.65,9.36 54.29,8.73
  Top 0.61: 50.32,7.77 50.32,7.93 | 50.32,7.77 50.32,6.5 49.21,6.5 49.21,10.15 | 41.91,13.49 41.91,13.17 42.7,12.38 42.7,10.47 44.6,10.47 45.72,11.58 | 43.81,13.49 IC4.5 | 43.81,13.49 43.81,11.27 C9.1 43.3,11.45 43.18,11.58 45.72,11.58 | IC5.1 54.29,8.73 54.29,9.36 51.27,9.36 | 49.84,9.36 50.16,9.36 | 50.16,9.36 51.27,9.36 | 49.84,9.36 49.21,10 49.21,10.15 | 49.21,11.27 49.21,10.15 | C10.2 50.16,7.14 49.84,7.46 49.84,9.36 | 45.72,11.58 43.81,13.49 | 50.16,9.36 49.84,9.68 49.53,9.68 49.37,9.84 | 50.32,7.77 50.32,8.41 51.27,9.36
N$133
  Top 0.61: 49.68,8.09 49.68,9.36
N$134
  Top 0.61: 50,8.57 50.48,9.04
N$135
  Top 0.61: R4.1 52.07,11.27 52.54,11.27 | 53.02,11.27 54.92,11.27 55.56,10.63 IC5.2 55.56,7.14 54.92,6.5 53.49,6.5 | 53.02,11.27 52.54,11.27 | 52.38,6.5 52.07,6.5 52.7,7.14 C10.1 | 52.38,6.5 53.49,6.5 | 52.38,6.5 51.91,6.5 51.91,7.77 53.02,7.77 53.02,6.98 53.49,6.5 | 52.54,11.27 52.07,10.79 50.8,10.79 50.8,12.06 52.22,12.06 | 52.22,12.06 | 53.02,11.27 52.22,12.06
N$136
  Top 0.406: 53.81,13.01 53.81,14.44
N$137
  Top 0.61: 58.1,9.52 58.57,9.52 58.89,9.2 61.11,9.2 61.11,5.71 58.73,3.33 37.78,3.33 36.67,4.44
N$138
  Top 0.61: 58.57,8.88 58.57,9.2
N$139
  Top 0.61: 59.21,11.27 59.69,10.79 60.96,10.79 61.91,11.74
N$140
  Top 0.813: 61.27,11.74 61.91,12.38
N$141
  Top 0.813: 58.26,11.9 59.37,11.9
N$142
  Top 1.422: 58.89,8.09 58.89,5.07 57.62,3.8
N$143
  Top 1.422: 60.16,6.34 60.16,5.55 58.57,3.96
N$144
  Top 0.254: 54.45,17.77 55.56,17.77 55.56,16.03
N$145
  Top 0.254: 53.97,17.61 53.97,16.19 54.92,16.19
N$146
  Top 0.254: 58.41,16.5 58.41,17.77 56.83,17.77 56.83,16.03
N$147
  Top 0.305: 52.86,28.57 52.86,34.76 52.38,35.24 50.8,35.24 50.8,33.65 51.91,32.54 51.91,28.57 52.86,28.57
N$148
  Top 0.61: 52.54,33.65 52.54,34.76
N$149
  Top 0.61: 51.91,33.01 51.27,33.65
N$150
  Top 0.305: 46.67,32.22 46.51,32.22 | 46.67,32.22 47.3,32.22 47.78,31.74 47.78,28.73 46.83,28.73 46.83,29.68 45.87,30.63 44.92,30.63 44.92,32.22 46.67,32.22
N$151
  Top 0.61: 46.03,30.79 46.83,30
N$152
  Top 0.61: 46.67,31.43 46.67,32.06
N$153
  Top 0.61: 47.14,31.74 47.14,31.9
N$154
  Top 0.61: 47.46,31.58 47.46,31.74
N$155
  Top 0.61: 54.92,25.87 54.92,26.35
N$156
  Top 0.254: 42.7,33.33 44.45,35.08 47.78,35.08 47.94,35.24 49.53,35.24 49.53,33.49 43.33,33.49
N$157
  Top 0.406: 46.51,33.65 47.94,33.65
N$158
  Top 0.406: 43.81,34.12 44.6,34.92
N$159
  Top 0.406: 44.13,34.12 44.76,34.76
N$160
  Top 0.406: 44.6,34.12 44.92,34.44
N$161  (via drill 0.5, 0.6, 0.7)
  Top 0.254: v46.67,49.05 C26.2
  Top 0.406: 35.87,13.49 35.24,12.85 v35.24,11.42 | v46.83,38.57 C27.2 | 35.87,24.6 35.87,24.12 35.55,23.81 | 35.55,23.81 | 35.55,23.81 35.4,23.65
  Top 0.61: 50.8,57.46 50.48,57.46 50.32,57.3 50.32,55.24 50.48,55.08 52.38,55.08 | 36.98,25.23 35.87,25.23 35.87,24.6 35.87,23.33 C29.2 | 36.98,25.23 IC3.4 | 35.87,13.49 IC4.4 | 35.55,11.58 35.87,11.27 35.87,13.49 | C34.1 60.32,8.41 60.06,8.67 IC5.4 58.1,5.23 56.51,3.64 | 35.55,10.95 35.55,10.63 36.83,9.36 36.83,8.09 | 52.07,44.6 IC7.4 | v53.34,45.87 52.07,44.6 | v53.34,56.35 53.34,55.4 53.02,55.08 52.7,55.08 | 51.43,55.08 IC6.4 52.38,55.08 | 52.7,55.08 52.38,55.08 | 36.03,24.28 36.03,22.38 33.97,22.38 33.81,22.54 33.81,23.33 34.13,23.65 35.4,23.65 36.03,24.28 | 36.98,25.23 36.03,24.28 | 35.87,13.49 34.76,13.49 34.6,13.33 34.6,11.11 36.51,9.2 36.51,4.6 | 52.07,44.6 53.81,44.6 53.97,44.76 53.97,46.51 53.81,46.67 53.18,46.67 51.27,44.76 | 52.7,55.08 54.61,55.08 54.76,55.24 54.76,57.3 54.61,57.46 50.8,57.46 | 50.8,57.46 50.64,57.3
  Top 0.813: 71.91,30.31 73.02,30.31 73.5,30.31 73.5,28.57
  Top 1.016: C30.2 35.55,11.58 35.55,10.95 | 36.83,8.09 36.83,4.6 37.78,3.64 56.51,3.64
  Top 1.27: 35.55,23.01 C29.2 v34.29,23.01 | 73.02,30.31 73.02,28.09
  Top 1.422: JP1.6 71.43,16.66 v72.7,17.93 73.34,18.57 73.34,27.77 73.02,28.09 71.11,30 71.58,29.51 C24.- | C34.1 v60.32,6.82
  Bottom 0.254: v35.24,11.42 35.24,22.06 v34.29,23.01 34.29,33.81 36.19,35.71 43.97,35.71 v46.83,38.57 50.8,38.57 53.34,41.11 v53.34,45.87 | v53.34,45.87 v53.34,56.35 | v46.67,49.05 50.16,49.05 v53.34,45.87 | v60.32,6.82 68.89,6.82 73.02,10.95 73.02,17.61 v72.7,17.93
N$162
  Top 1.016: 42.86,33.97 37.14,33.97 35.87,32.7
N$163
  Top 1.422: 35.71,29.52 35.71,32.54
N$164
  Top 0.406: 52.07,21.9 52.07,24.12 | 52.07,21.9 51.43,21.27 | 51.91,21.9 52.07,21.9 | 51.91,21.9 51.27,21.27 51.27,20 52.7,20 | 51.91,21.9 52.22,22.22
N$165
  Top 0.305: 42.54,31.9 43.49,31.9 43.65,31.74
N$166
  Top 0.406: 43.49,30.63 43.65,30.79
N$167
  Top 0.406: 43.65,30.47 43.65,30.63
N$168
  Top 0.406: 42.54,30.47 43.49,30.47
N$169
  Top 0.305: 29.36,13.65 29.36,13.96
N$170
  Top 0.254: 41.27,27.93 41.91,27.93
N$171
  Top 0.254: 41.27,27.62 41.91,27.62
N$172
  Top 1.422: 31.27,12.54 31.27,16.19
N$173
  Top 0.61: 37.78,13.49 36.98,13.49 36.35,12.85 36.35,10 37.14,9.2 37.14,4.6
N$174
  Top 0.406: 40.32,27.14 40.32,26.82 40.64,26.82
N$175
  Top 0.813: 40.48,26.66 40.48,23.96 40.64,23.81
N$176
  Top 0.813: 39.05,23.65 39.84,23.65
N$177
  Top 0.813: 39.05,22.54 39.84,22.54
N$178
  Top 0.305: 34.76,26.66 33.81,25.71 33.81,24.76 34.76,24.76 34.76,25.71 35.4,26.35 35.24,26.35 34.6,25.71
  Top 0.406: 34.6,25.71 34.6,24.92 33.97,24.92 33.97,25.71
N$179
  Top 0.61: 36.19,24.92 36.35,25.08
N$180
  Top 0.406: 30.16,23.49 31.9,23.49 32.06,23.33 32.06,22.22
N$181
  Top 0.406: 31.74,22.38 31.74,23.17
N$182
  Top 0.406: 30.32,22.7 30.16,22.7 29.68,22.22
N$183
  Top 0.61: 36.51,13.17 35.08,13.17 35.08,11.11
N$184
  Top 0.61: 35.55,12.22 35.55,12.69
N$185
  Top 1.676: 32.7,10.79 32.7,13.65
N$186
  Top 0.813: 31.9,11.9 31.9,12.22
N$187
  Top 0.406: 33.49,13.96 33.65,13.96
N$188
  Top 0.406: 27.14,14.44 28.73,14.44
N$189
  Top 0.61: 28.25,14.6 27.78,15.08
N$190
  Top 0.61: 29.84,16.98 30.47,16.98
N$191
  Top 0.305: 57.15,21.42 57.15,21.27 60.48,21.27 60.64,21.42 60.64,25.71 61.27,26.35 62.7,26.35 63.65,27.3 63.65,28.25 60.48,28.25 59.21,26.98
N$192
  Top 0.813: 61.91,27.14 63.02,27.14
N$193
  Top 0.813: 61.91,26.66 62.54,26.66
N$194
  Top 0.813: 60.32,27.46 60.32,27.62
N$195
  Top 0.813: 60.32,27.3 60,27.3
N$196
  Top 0.813: 60.32,21.58 60.32,26.19
N$197
  Top 0.813: 58.26,26.19 60.64,26.19
N$198
  Top 0.813: 57.3,32.06 57.78,32.54 62.54,32.54 62.86,32.22 62.86,30.79 62.38,30.31 60,30.31 58.41,28.73 57.3,28.73 57.3,32.06
N$199
  Top 0.813: 57.78,31.9 57.94,31.9 62.38,31.9
  Top 1.93: 57.94,31.9 57.94,29.36
N$200
  Top 1.016: 58.41,29.2 58.41,30.47
N$201
  Top 1.016: 59.05,30 59.37,30.31
N$202
  Top 0.61: 62.23,22.54 66.19,22.54 66.19,21.11 62.23,21.11 62.23,22.54
N$203
  Top 0.61: 64.77,26.35 64.77,27.14 65.72,27.14 65.72,24.12 62.38,24.12
N$204
  Top 1.016: 65.24,25.87 65.24,24.6 63.65,24.6
N$205
  Top 1.016: 64.61,25.08 65.08,25.55
N$206
  Top 0.61: 27.62,26.98 27.62,28.09
N$207  (via drill 0.7)
  Top 0.254: 67.78,24.92 67.7,24.84 67.62,24.76 67.46,24.76
  Top 1.016: 68.57,21.74 68.57,31.43 67.46,31.43 67.46,24.76 67.94,24.28 67.94,21.42 68.57,21.42 | D1.C 57.58,31.06 57.46,30.95 K1.1 57.46,30 | v67.62,31.27 67.62,24.92 67.7,24.84 68.26,24.28 JP1.2
  Top 1.27: D1.C 61.27,31.27 v62.23,31.27
  Bottom 0.254: v62.23,31.27 v67.62,31.27
N$208
  Top 0.813: 72.7,29.2 72.7,29.84 72.38,29.84
N$209
  Top 1.016: 65.24,5.39 64.61,5.39 61.27,2.06
N$210
  Top 1.016: 66.35,5.71 67.3,6.66
N$211
  Top 1.016: 66.51,5.71 66.51,2.22 66.03,1.74 62.07,1.74 | 68.57,11.9 67.94,11.9 67.94,10 67.15,9.2 66.35,9.2 66.35,6.82 65.4,5.87 63.97,5.87 59.84,1.74 | 68.57,11.9 68.57,10.79 | 29.2,7.46 29.2,4.92 29.2,4.6 32.06,1.74 34.13,1.74 | R22.2 66.67,8.73 66.67,7.77 | 65.4,4.6 65.08,4.6 62.23,1.74 62.07,1.74 | 34.13,1.74 59.84,1.74 | 59.84,1.74 62.07,1.74 | 68.57,11.9 69.21,11.9 69.21,8.57 67.15,6.5 | 34.13,1.74 6.98,1.74 6.98,6.34 6.03,7.3
  Top 1.27: 29.2,7.46 6.03,7.46 4.76,8.73 4.76,16.98 5.39,17.61 | 29.2,7.46 R24.E | 5.39,17.61 6.03,18.25 13.97,18.25 14.28,18.57 14.28,20.47 14.28,23.33 | 8.09,20.31 5.39,17.61 | 29.2,7.46 | 29.2,7.46 29.36,7.3 29.36,4.28 30.32,3.33 34.6,3.33 36.03,1.9 | 29.2,4.92 29.2,4.76 30.79,3.17 | 3.49,30.31 1.74,30.31 1.74,6.98 1.9,6.82 6.03,6.82 7.46,5.39
  Top 1.422: L1.2 16.5,29.04 15.87,28.41 15.87,24.92 | 15.87,24.92 15.87,24.28 15.24,23.65 | 15.24,23.65 14.92,23.33 14.28,23.33 10.16,23.33 9.2,24.28 9.2,25.87 | 9.2,25.87 C25.+ | L2.2 9.2,25.87 | R22.2 66.99,8.73 68.26,10 JP1.10 | C31.+ 65.4,4.6 66.67,6.5 66.67,7.77 | L2.2 9.36,30.31 9.36,24.12 | 8.41,30.31 8.09,30.31 8.09,20.31 8.09,18.57 | 8.41,30.31 L2.2 | 15.24,23.65 14.12,22.54 | 15.87,24.92 15.87,22.06 14.28,20.47 | 8.41,30.31 3.49,30.31 1.9,30.31 1.9,8.41
N$212
  Top 1.422: 65.88,3.17 65.88,3.33 65.24,3.33 65.08,3.49
N$213
  Top 1.422: 63.81,2.53 65.88,2.53
N$214
  Top 1.422: 67.62,7.77 68.89,9.04
N$215
  Top 1.27: 67.15,13.96 66.67,13.96 65.88,13.17
N$216
  Top 0.406: 74.29,32.54 70.32,32.54 69.84,33.01
N$217
  Top 0.406: 73.66,33.65 65.56,33.65 64.77,32.85 64.77,28.73
N$218  (via drill 0.7)
  Top 0.254: 40.95,30 41.27,30.31 43.65,30.31 43.81,30.47 43.81,31.9 43.65,32.06 40.95,32.06 40.95,30.31
  Top 0.305: 40.95,16.82 40.95,16.66 41.27,16.34 | 41.27,16.34 | 41.27,16.34 41.43,16.19 52.86,16.19 54.13,14.92 54.45,14.92 54.45,12.85 53.65,12.85 53.65,14.92
  Top 0.406: 41.11,20 43.65,20 43.81,19.84 43.81,18.57 43.65,18.41 41.43,18.41 40.95,17.93 | IC3.7 41.27,27.77 40.95,28.09 40.95,30 40.95,30.31 41.59,30.95 C11.2 | IC4.7 41.27,16.03 40.95,16.34 40.95,16.82 40.95,17.93 | C12.2 41.59,18.88 40.95,18.25 40.95,17.93
  Top 0.61: IC4.7 52.7,16.03 54.29,14.44 IC5.8 54.29,13.81 | 44.45,40.79 45.24,40.79 | 45.24,40.79 IC7.8 | 44.45,40.79 44.13,40.48 44.13,38.89 43.81,38.57 C27.1 | IC6.8 44.45,51.27 44.13,50.95 44.13,49.37 43.81,49.05 C26.1 | 45.24,40.79 44.76,40.79 44.29,40.32 44.29,37.94 41.59,37.94 41.43,38.09 41.43,40.48 41.75,40.79 44.45,40.79
  Top 1.27: v43.18,31.27 C11.2 | C12.2 v43.18,19.2 | v42.22,49.05 43.81,49.05
  Top 1.422: v42.22,38.57 C27.1 | JP1.4 69.84,19.2 70.8,20.15 v70.8,22.38 C24.+
  Bottom 0.254: v42.22,49.05 v42.22,38.57 43.18,37.62 v43.18,31.27 v43.18,19.2 47.62,23.65 69.53,23.65 v70.8,22.38
N$219
  Top 0.406: 43.65,18.57 43.65,19.84
N$220
  Top 0.406: 37.3,17.46 37.3,20.15
N$221
  Top 0.305: 49.84,20 | 49.84,20 49.05,19.2
  Top 0.406: 37.14,19.2 37.14,20.15 | 37.14,20.15 38.1,21.11 44.45,21.11 | 44.45,21.11 44.76,21.11 45.08,20.79 45.08,20.47 | 45.08,20.47 45.08,19.84 | 45.08,19.84 45.08,19.2 45.4,19.2 | 45.4,19.2 49.05,19.2 49.84,19.2 49.84,19.52 | 38.41,17.3 37.62,17.3 37.14,17.77 36.83,17.46 | 36.83,17.46 36.83,17.3 | 36.98,17.46 36.98,20 37.14,20.15 | 36.83,17.46 36.83,19.84 37.14,20.15 | 45.08,19.84 45.08,19.52 45.4,19.2 | 44.45,21.11 45.08,20.47
  Top 0.61: IC4.1 37.14,17.3 37.14,17.77 37.14,19.2
  Top 1.016: 49.84,19.52 49.84,20 K1.9
N$222
  Top 0.61: 52.7,20.15 52.7,24.12
N$223
  Top 0.813: 44.92,17.77 45.08,17.77 45.24,17.93 46.83,17.93
N$224
  Top 0.406: 47.94,20.95 47.94,21.27 47.46,21.74
N$225
  Top 0.406: 46.67,20.95 46.67,21.27 46.98,21.58
N$226
  Top 0.61: 42.22,25.23 42.22,24.6 42.54,24.28 | 42.54,24.28 | 42.54,24.28 42.7,24.12 42.7,22.38 45.08,22.38 45.56,22.85 45.56,24.44 46.35,25.23 | 43.49,25.23 43.81,25.23 43.81,23.01 C5.1 | 43.49,25.23 IC3.5 | IC5.7 55.56,15.71 54.61,16.66 C6.2 54.79,17.11 53.97,17.93 53.97,18.88 | 53.97,18.88 53.97,24.6 53.34,25.23 46.35,25.23 | 43.49,25.23 46.35,25.23 | 53.97,18.88 53.97,18.57 54.92,17.61
N$227
  Top 1.016: 45.24,23.01 45.24,24.76
N$228
  Top 1.016: 44.45,22.7 44.45,24.76
N$229
  Top 1.016: 43.18,24.12 43.18,24.76
N$230
  Top 1.016: 42.86,24.92 42.7,24.92
N$231
  Top 0.406: 13.81,43.97 14.44,43.33 14.44,41.74
N$232
  Top 0.305: 40.64,36.66 39.84,37.46 39.84,40.48 38.25,40.48 38.25,37.3 39.37,36.19 39.84,36.19
N$233
  Top 0.406: 39.52,36.35 38.57,37.3 38.57,38.89
N$234
  Top 0.406: 39.68,37.62 39.68,38.89
N$235
  Top 0.406: 39.68,37.46 39.68,37.3 40.16,36.82
N$236
  Top 0.61: 50.8,40.79 50.95,40.79 51.59,40.16 51.59,37.3 50.8,36.51
N$237
  Top 0.61: 52.22,39.2 52.22,40.63
N$238
  Top 0.813: 52.7,40 52.7,39.68 53.18,39.2
N$239
  Top 0.813: 53.02,36.66 54.29,37.94
N$240
  Top 0.813: 52.7,37.3 53.49,38.09
N$241
  Top 0.406: 49.05,40.32 50,39.36 50,37.78 48.73,37.78 48.73,42.06
N$242
  Top 0.61: 49.21,39.84 49.21,39.68 49.68,39.2
N$243
  Top 0.406: 66.51,38.89 72.54,38.89 72.54,37.62 66.51,37.62 66.51,38.89
N$244
  Top 0.406: 61.11,40.16 61.11,43.33 59.84,43.33 59.84,39.36 61.59,37.62 64.92,37.62 64.92,38.89 62.54,38.89 62.38,39.05
N$245
  Top 0.813: 60.16,39.68 | 61.91,37.94 60.16,39.68
N$246
  Top 0.406: 58.26,40.95 58.26,39.36 56.99,39.36 55.24,41.11 | 58.26,40.95 | 58.26,40.95 56.99,42.22
N$247
  Top 0.406: 50.64,42.22 56.99,42.22
N$248
  Top 0.406: 55.4,40.95 53.81,40.95 53.81,41.43 53.18,42.06
  Top 0.61: IC7.2 53.18,42.06 53.97,42.06 54.61,41.43
  Top 1.27: R15.2 57.46,40.16 56.19,41.43 54.61,41.43 R16.2
N$249
  Top 0.61: 56.67,41.9 56.99,41.9 57.94,40.95
N$250
  Top 0.61: 55.88,40.79 56.83,39.84
N$251
  Top 0.61: 53.65,46.35 53.49,46.35 52.07,44.92
N$252
  Top 0.61: 53.65,45.87 53.65,44.92 53.18,44.92
N$253
  Top 0.61: 53.49,45.24 53.18,45.24 52.86,44.92
N$254
  Top 0.61: 52.22,51.27 52.38,51.27 53.81,49.84 | 53.81,49.84 | 53.81,49.84 53.97,49.68
N$255
  Top 0.61: 58.89,42.7 57.78,43.81
N$256
  Top 0.406: 52.38,49.84 52.38,50.79
N$257
  Top 0.61: 52.22,50.79 | 53.34,49.68 52.22,50.79
N$258
  Top 0.61: 52.54,50 52.54,50.16
N$259
  Top 0.61: 52.86,48.57 54.29,48.57
N$260
  Top 0.61: 51.75,47.78 51.75,48.41
N$261
  Top 0.61: 51.27,47.3 51.91,47.94
N$262
  Top 1.27: 36.35,33.65 36.35,29.52
N$263
  Top 0.406: 52.86,52.38 54.13,51.11 57.62,51.11 57.62,52.7 50.64,52.7
N$264
  Top 0.406: 55.4,51.43 56.35,51.43
N$265
  Top 0.61: 53.49,51.91 53.49,52.38
N$266
  Top 0.61: 58.89,49.37 58.73,49.52
N$267
  Top 0.61: 57.94,47.62 59.53,47.62
N$268
  Top 0.61: 58.41,47.94 58.41,48.09
N$269
  Top 0.254: 63.02,46.67 63.02,49.21 62.86,49.37 61.43,49.37 61.27,49.21 61.27,46.98 60.32,46.03 59.05,46.03 59.05,44.44 61.59,44.44 62.07,43.97 62.07,43.17 | 63.02,46.67 63.02,46.51 | 63.02,46.67 63.18,46.51 63.18,45.4 | 63.18,45.4 63.18,45.24 63.02,45.08 63.02,43.65 64.13,42.54 | 63.18,43.33 63.18,45.4
N$270
  Top 0.61: 61.91,44.44 61.59,44.76 60.8,44.76
N$271
  Top 0.61: 62.7,46.51 62.7,49.05
N$272
  Top 0.61: 61.59,46.03 61.59,47.62
N$273
  Top 0.61: 60.64,46.03 61.27,46.67
N$274
  Top 0.813: 60.8,45.55 61.43,46.19
N$275
  Top 0: 59.21,52.54 59.05,52.7
  Top 0.406: 63.18,50.95 59.37,50.95 59.21,51.11 59.21,52.54 59.21,52.7 64.61,52.7 64.92,52.38 64.92,45.4
N$276
  Top 0.406: 60.48,51.11 62.38,51.11
N$277
  Top 0.406: 63.5,52.38 64.61,52.38 64.61,50.95
N$278
  Top 1.422: 9.2,22.85 9.2,23.65
N$279
  Top 1.27: 72.07,50.95 72.07,44.6 | 72.07,50.95 | 72.07,50.95 70.32,52.7 67.15,52.7 66.67,52.22 66.67,45.08 67.15,44.6 72.54,44.6 73.02,45.08 73.02,50 72.07,50.95
N$280
  Top 0.813: 63.5,42.54 62.86,43.17
N$281
  Top 0.305: 32.54,40.32 32.22,40.32
  Top 0.406: 25.39,30.79 26.66,30.79 27.3,30.16 27.3,26.03 29.05,26.03 30,25.08 31.59,25.08 31.59,27.14 33.17,28.73 33.17,33.33 36.67,36.82 36.67,38.89 36.35,39.2 33.65,39.2 32.54,40.32 30.95,40.32 30.95,39.68 30.79,39.68 30.47,39.36
N$282
  Top 1.27: 13.17,30.47 13.97,30.47
N$283
  Top 0.305: 31.11,40.32 31.11,40.16 30.16,39.2 | 30.16,39.2 30,39.05 | 30.16,39.2 27.46,39.2 25.24,36.98
N$284
  Top 0.61: 27.78,30.31 26.82,31.27
N$285
  Top 0.813: 31.43,27.62 32.7,28.89
N$286
  Top 0.813: 32.06,29.04 31.43,28.41
N$287
  Top 0.813: 32.38,39.84 33.33,38.89
N$288
  Top 0.813: 25.87,36.98 27.14,38.25
N$289
  Top 0.813: 27.46,37.62 26.82,36.98
N$290
  Top 1.016: 32.86,33.81 35.71,36.66
N$291
  Top 1.016: 33.02,34.92 34.6,36.51
N$292
  Top 1.016: 32.86,35.71 33.81,36.66
N$293
  Top 1.422: 15.24,22.7 14.6,22.06
N$294
  Top 0.305: 43.18,55.56 43.18,56.67 41.43,56.67 41.43,55.08 43.33,55.08
N$295
  Top 0.61: 70.16,5.07 68.57,5.07 68.57,1.74 68.89,1.42 73.18,1.42 73.18,4.44 arc-125 77.78,6.5
N$296
  Top 1.27: 78.58,39.05 78.58,39.2 | 78.58,39.05 78.58,6.82 arc104 72.86,2.22 | 78.58,39.05 78.58,52.54 75.56,52.54 75.56,44.92 | 75.56,44.92 75.56,44.76 76.99,43.33 | 75.56,44.92 75.56,43.49 73.97,41.9
N$297
  Top 1.27: 73.97,6.82 78.42,6.82
N$298
  Top 1.27: 29.05,2.38 34.76,2.38
N$299
  Top 1.27: 29.2,2.69 29.2,3.64
N$300
  Top 1.27: 7.14,2.53 arc94 3.17,6.98
N$301
  Top 0.61: 32.38,46.82 32.38,49.52
N$302
  Top 0.61: 32.38,49.52 31.9,50 23.33,50
N$303
  Top 1.016: 22.54,48.73 31.9,48.73 31.9,48.25
N$304
  Top 1.27: 2.85,50.48 32.06,50.48 32.06,47.14
N$305
  Top 1.27: 12.38,36.82 12.06,36.82 11.11,35.87
N$306
  Top 1.27: 6.5,42.38 8.41,44.28
N$307
  Top 1.27: 6.98,44.6 6.98,43.81 7.14,43.65
N$308
  Top 0.305: 59.53,18.09 59.53,16.66 61.11,16.66 61.11,18.41 59.37,18.41
N$309
  Top 0.406: 60.96,19.84 56.35,19.84
N$310
  Top 0.406: 64.45,16.34 64.45,16.19 63.65,15.39
N$311
  Top 0.61: 29.36,26.35 30.32,25.39
N$312
  Top 1.27: 59.53,8.73 59.53,5.39
N$313
  Top 3.81: 10.31,46.51 4.28,40.48
N$314
  Top 1.27: 22.7,17.93 24.28,16.34 24.28,16.19 | 24.28,16.19 24.28,15.55 | 24.28,16.19 24.28,15.39
N$315  (via drill 0.5, 0.6, 0.7)  (3 unrouted)
  Top 0.254: 37.78,22.22 41.27,22.22 41.27,23.81 40.95,24.12 40.95,26.66 40,27.62 | 39.68,30.79 39.68,32.06 38.1,32.06 38.1,30.47 39.52,30.47 | 39.52,30.47 39.84,30.47 | 35.87,16.98 36.19,16.66 36.35,16.66 | 39.52,16.66 40,16.66 | 36.35,16.66 39.52,16.66 | 31.74,14.44 32.06,14.12 33.49,14.12 | 33.97,14.12 33.49,14.12 | 39.52,14.12 33.97,14.12 | 40,14.12 39.52,14.12 | v39.37,23.01 40,23.65 40,24.28 39.68,23.96 37.62,23.96 37.46,23.81 37.46,22.22 35.71,20.47 35.71,16.98 36.03,16.66 36.35,16.66 | 74.45,15.55 74.61,15.39 v74.29,15.39 | 74.45,15.55 | C16.2 31.61,47.27 30.79,48.09 29.84,49.05 | C17.2 31.46,39.71 30.63,38.89 30.63,31.58 30.79,31.43 25.87,31.43 v25.71,31.58 | v17.46,31.58 15.55,31.58 X2.5 | 39.52,30.47 | 40,30 39.52,30.47 | 31.74,16.03 31.74,15.87 33.49,14.12 | 33.97,14.12 33.49,13.65 33.49,10.31 | 39.52,16.66 39.84,16.98 | 39.84,16.98 | 39.84,16.98 40,17.14 | 39.52,16.66 39.84,16.34 | 39.52,14.12 39.84,14.44 | 40,13.65 39.52,14.12
  Top 0.305: 30.63,11.74 29.2,11.74 29.2,13.65 28.73,14.12
  Top 0.406: 41.11,12.06 41.11,10.47 40.95,10.31 38.1,10.31 37.94,10.47 37.94,12.06 39.21,12.06 40,12.85 | C11.1 39.05,31.27 40,30.31 40,30 40,27.62 40,24.28 40,23.01 | C12.1 39.23,19.02 40,18.25 40,17.14 40,16.66 40,15.55 | 40,13.17 40,13.65 40,14.12 40,15.55 | 40,13.17 40,12.85 | 40,12.85 40,11.27 | C29.1 38.23,22.82 35.87,20.47 | 35.87,20.47 35.87,16.98 | 23.01,14.12 22.54,14.12 22.54,14.28 | 38.41,23.01 35.87,20.47 | 26.66,14.12 23.01,14.12 | 26.66,14.12 28.73,14.12 29.52,14.12 | 23.01,14.12 22.54,14.12 18.57,18.09 | 23.01,14.12 22.22,14.92 | 27.62,15.08 26.66,14.12 | 41.11,12.06 | 41.11,12.06 40,13.17 | 40.64,12.38 40.64,14.92 40,15.55
  Top 0.61: C11.1 38.92,30.76 | C7.2 31.56,17.17 31.74,16.98 31.74,16.66 | 31.74,16.66 31.74,16.03 31.74,15.23 31.74,14.44 | 26.98,48.09 IC2.8 22.22,48.09 22.22,48.73 21.58,49.37 21.58,49.68 | 26.98,48.09 27.3,48.09 27.62,48.41 28.89,48.41 29.2,48.73 29.07,48.86 C18.2 | 29.52,14.44 29.52,14.12 | 19.36,18.25 22.54,15.08 22.54,14.28 | 27.62,14.28 27.62,15.08 27.62,16.82 29.36,16.82 30.16,17.61 30.16,17.77 31.74,17.77 31.74,16.66 | 26.98,48.09 30.79,48.09
  Top 0.813: 64.92,28.73 64.92,28.57 65.72,28.57 65.72,32.22 66.67,33.17
  Top 1.016: OUT_GND.1 66.67,33.17 65.72,33.17 65.08,32.54 65.08,28.73 65.08,28.72 T1.E | 31.74,15.23 32.54,14.44 | C35.2 62.04,46.54 62.55,46.03 C14.2 | C36.2 61.91,45.24 C14.2 | C15.2 C14.2
  Top 1.27: v25.71,31.58 29.68,31.58 | 29.68,31.58 X3.4 | C29.1 38.41,23.01 v39.37,23.01 40,23.01 C5.2 | C8.2 30.79,26.19 30.34,26.63 C4.2 28.25,28.41 | C7.2 30.79,17.3 30.66,16.21 29.84,16.21 | 29.84,16.21 C3.2 28.25,15.71 29.52,14.44 | C30.1 40,11.27 C9.2 | 29.36,36.66 X3.3 30.79,35.55 | 29.36,36.66 X3.2 | 31.74,49.68 21.58,49.68 16.82,49.68 16.19,49.05 16.19,42.7 15.68,42.19 C13.1 15.24,43.65 14.28,44.6 10.47,44.6 6.66,40.79 6.66,36.98 7.93,35.71 12.38,35.71 | C2.2 27.93,28.73 28.25,28.41 | C2.2 28.06,31.08 28.25,31.27 30.47,31.27 X3.4 | X3.4 30.79,33.01 | 30.79,33.01 30.79,35.55 | 29.84,16.21 29.84,16.03 29.97,15.9 C1.2 30.47,12.54 34.29,8.73 R24.A | 28.25,28.41 28.25,28.54 C2.2 | 28.25,28.41 v30.16,28.41 | OUT_GND.1 73.66,33.17 73.97,33.49 | 73.97,33.49 74.61,34.12 74.61,41.11 73.66,42.06 IN_GND.1 62.54,42.06 | 72.86,14.12 73.02,14.12 v74.29,15.39 74.45,15.55 75.88,16.98 75.88,31.58 73.97,33.49 | JP1.8 JP1.7 | 69.84,14.12 70,14.12 71.27,12.85 | 62.54,42.06 | 62.54,42.06 63.65,40.95 73.66,40.95 74.45,40.16 | 15.55,31.58 13.65,29.68 13.65,25.55 12.06,25.55 12.06,31.27 10.63,32.7 7.93,32.7 | 7.93,32.7 7.14,32.7 | 12.38,32.7 13.65,31.43 | 14.12,36.66 13.49,36.66 12.38,35.55 | 29.36,36.66 29.68,36.66 30.79,35.55 | 30.79,33.01 30.79,32.7 29.68,31.58 | 7.93,32.7 1.74,32.7 1.74,49.37 2.69,50.32
  Top 1.422: X2.2 14.12,36.66 X2.3 | X2.5 12.38,35.55 | 12.38,35.55 X2.2 | v17.46,31.58 X2.5 | C16.2 31.74,47.46 30.34,48.86 C18.2 | C17.2 31.74,39.52 30.79,38.57 | C19.2 30.66,38.44 30.79,38.57 | X3.3 30.79,38.57 | C25.- 12.84,31.44 13.33,31.58 X2.5 | X2.5 12.38,32.7 12.38,35.55 | 12.38,35.55 12.38,35.71 X2.2 | C31.- 70.16,4.6 71.43,5.87 71.43,13.81 71.11,14.12 69.84,14.12
  Top 1.676: X1.3 X1.4 X1.3 | X1.3 7.62,10.31 X1.5 | JP1.9 JP1.7 JP1.8 69.84,14.12 72.86,14.12
  Bottom 0.254: v30.16,28.41 33.97,28.41 v39.37,23.01 40.64,21.74 59.37,21.74 63.18,17.93 71.75,17.93 v74.29,15.39 | v17.46,31.58 v25.71,31.58
  Bottom 1.27: v17.46,31.58 v25.71,31.58
N$316
  Top 0.406: 40.32,14.92 40.32,12.06 40.64,12.06
N$317
  Top 0.406: 39.84,12.22 39.21,11.58
N$318
  Top 0.406: 39.05,10.63 40.16,10.63
N$319
  Top 1.93: 67.15,52.06 67.15,45.24
N$320
  Top 1.93: 56.67,41.43 57.46,40.63
N$321
  Top 1.93: 58.1,25.87 58.1,22.22
N$322
  Top 1.27: 36.83,33.97 35.24,32.38
N$323
  Top 0.406: 27.46,23.96 27.14,23.65 26.82,23.65 26.66,23.49 23.97,23.49
N$325  (via drill 0.8)  (1 unrouted)
  Top 0.406: 27.3,19.36 23.81,19.36 23.81,19.68 29.05,19.68 29.05,18.41 27.46,18.41 27.46,18.88 26.82,19.52
  Top 0.61: C3.1 v28.25,19.2 27.93,19.52 26.82,19.52 IC1.10 | v34.29,25.23 34.29,25.87 34.92,26.5 IC3.3 37.78,26.5
  Bottom 0.406: v28.25,19.2 v34.29,25.23
(copper drawn outside any net)
  shapes: Top area x26

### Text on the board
Top: QSD detector/exciter | 2008 | Michal Slomkowski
